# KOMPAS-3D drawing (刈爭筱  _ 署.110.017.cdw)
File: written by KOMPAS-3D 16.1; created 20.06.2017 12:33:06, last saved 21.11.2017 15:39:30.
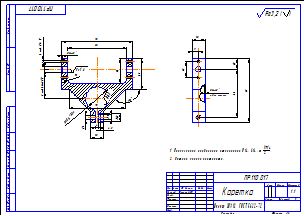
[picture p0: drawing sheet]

Sheet 1: A3, landscape

Title block, sheet 1: name: Каретка; designation: ПР.110.017; material: Полоса 30Х13  ГОСТ 5632-72; scale: 1:1; sheets: 1; sheet format: A3; stored path: D:\VSE\Эрга\Оснастка\Пронос\Каретка _ ПР.010.017.cdw; drawn by: Сигачев СИ

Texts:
  Сергей
  Ra1,6
  с 2-х сторон
  Неуказанные предельные отклонения H14, h14,    IT14 2 .
  Острые кромки притупить.
  Ra3,2
  Ra3,2 ( )
  CONTINUOUS_RGB_0_0_0_THICK_0.18
  CONTINUOUS_RGB_0_0_255_THICK_0.18
  CONTINUOUS_RGB_0_255_0_THICK_0.18
Dimensions and other numbers on the sheet: 5; 0,5; 82; 98; 0,63; -7H; 4 отв.; 3; 2 отв.; 8; 40±0,1; 33; 135; 6; 7; 12; 4,5; 18; 4; 78; 9; 22; 15; 66; 88; 43; 34; 1:1; 1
